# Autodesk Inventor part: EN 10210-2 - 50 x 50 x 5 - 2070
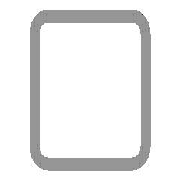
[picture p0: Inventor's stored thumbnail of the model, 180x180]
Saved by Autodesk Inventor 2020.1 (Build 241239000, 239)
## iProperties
_CCFamilyMember: 16
_CCFamilyDisplayName: DIN EN 10210-2 (USAS B17.1 quadratisch) - Rohrleitung — In Klammern angegebene Größen wurden aufgehoben
_FrameMemberDoc: Frame Member File
_Version: 15.0.0
_GetPNFromCC: 1
IsCustomPart: 1
Created: 2019-01
Part Number: EN 10210-2 - 50 x 50 x 5 - 2070
Material: Stahl, weich
Description: Rohrleitung
Document SubType Name: Modeling
Standard: DIN
Designer: lutzd
Standard Revision: 2006-07
Standards Organization: DIN
Language: de-DE
Size Designation: 50 x 50 x 5
Categories: <MemberInstance><Categories><Category DisplayName="Profile" InternalName="089c4875-fa83-4c05-b084-43b9cc11f5ed" Mnemonic="GRDR"><CategoryParameter DisplayName="
Stock Number: 50 x 50 x 5
Mass: 14188.7 g
Surface Area: 7025.24 cm^2
Volume: 1807.47 cm^3
Density: 7.85 g/cm^3
Appearance: Halbpoliert
G_L: 2070,000 mm
G_W: 50,000 mm
G_H: 50,000 mm
Dimensions: 50x50x2070 mm
Mass: 14,189 kg
DocNumber: ADSK-014097
Folder: .
+77706983-C492-4869-AC9B-676FE799CDC9+SCHNITTDETAIL1: Schnittwinkel 90,00 grd
+7E3252C6-52DF-4281-BFEF-A5744BDE2CB1+SCHNITTDETAIL2: Schnittwinkel 90,00 grd
Title: Profil-Bauteil
Author: lutzd
Revision Number: -
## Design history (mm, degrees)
node "Startebene"
node "Endebene"
sketch "Skizze"
  geometry: L1 (-25, -17.5)-(-25, 17.5); L2 (-17.5, 25)-(17.5, 25); L3 (25, 17.5)-(25, -17.5); L4 (17.5, -25)-(-17.5, -25); L5 (-15, 20)-(15, 20); L6 (20, 15)-(20, -15); L7 (15, -20)-(-15, -20); L8 (-20, -15)-(-20, 15); L9 (0, 37.175)-(0, -37.175) reference; L10 (-37.175, 0)-(37.175, 0) reference; A1 r 7.5 centre (-17.5, -17.5) between (-25, -17.5) and (-17.5, -25); A2 r 7.5 centre (-17.5, 17.5) between (-17.5, 25) and (-25, 17.5); A3 r 7.5 centre (17.5, 17.5) between (25, 17.5) and (17.5, 25); A4 r 7.5 centre (17.5, -17.5) between (17.5, -25) and (25, -17.5); A5 r 5 centre (-15, -15) between (-20, -15) and (-15, -20); A6 r 5 centre (-15, 15) between (-15, 20) and (-20, 15); A7 r 5 centre (15, 15) between (20, 15) and (15, 20); A8 r 5 centre (15, -15) between (15, -20) and (20, -15)
  constraints: 16 end point, 16 point on circle, 16 tangent, 8 centre point, 6 equal radius, 4 parallel, 2 perpendicular, 2 other
  dimensions: "d7" = 7.5 radius of A1 (= G_IR); "d10" = 50 distance between parallel lines of L2 L4 (= G_H); "d11" = 50 distance between parallel lines of L1 L3 (= G_W); "d12" = 5 distance between parallel lines of L3 L6 (= G_T); "d15" = 25 distance between parallel lines of L2 L10 (= 0.5 x d10); "d16" = 25 distance between parallel lines of L9 L3 (= 0.5 x d11); "d19" = 5 radius of A5 (= G_T); "d20" = 5 distance between parallel lines of L4 L7 (= G_T)
extrude "Körper" new body sketch "Skizze" stored distance "d3" = 2070 (= G_L); taper "d4" = 0 deg
node "Driven Length"
  sketch "Sketch3"
    geometry: L1 (0, 0)-(10, 0) reference
    constraints: 2 end point, 1 horizontal
  workplane "Work Plane3"
  sketch "Sketch4"
    geometry: L1 (-2, 50)-(12, 50) reference; L2 (-2, 2120)-(12, 2120) reference
    dimensions: "d18" = 2070 distance between parallel lines of L1 L2 (derived)
workplane "Arbeitsebene4"
feature "Trennen1"
workplane "Arbeitsebene5"
feature "Trennen2"
body "Solid1"
other parameters: "G_W" = 50 [user parameter; used in 1 equation term], "G_H" = 50 [user parameter; used in 1 equation term], "G_T" = 5 [user parameter; used in 3 equation terms], "G_IR" = 7.5 [user parameter; used in 1 equation term], "G_L" = 2070 (= d18) [user parameter; used in 1 equation term], "d17" = 90 deg
